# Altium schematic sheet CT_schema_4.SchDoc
size 422 x 246 mm
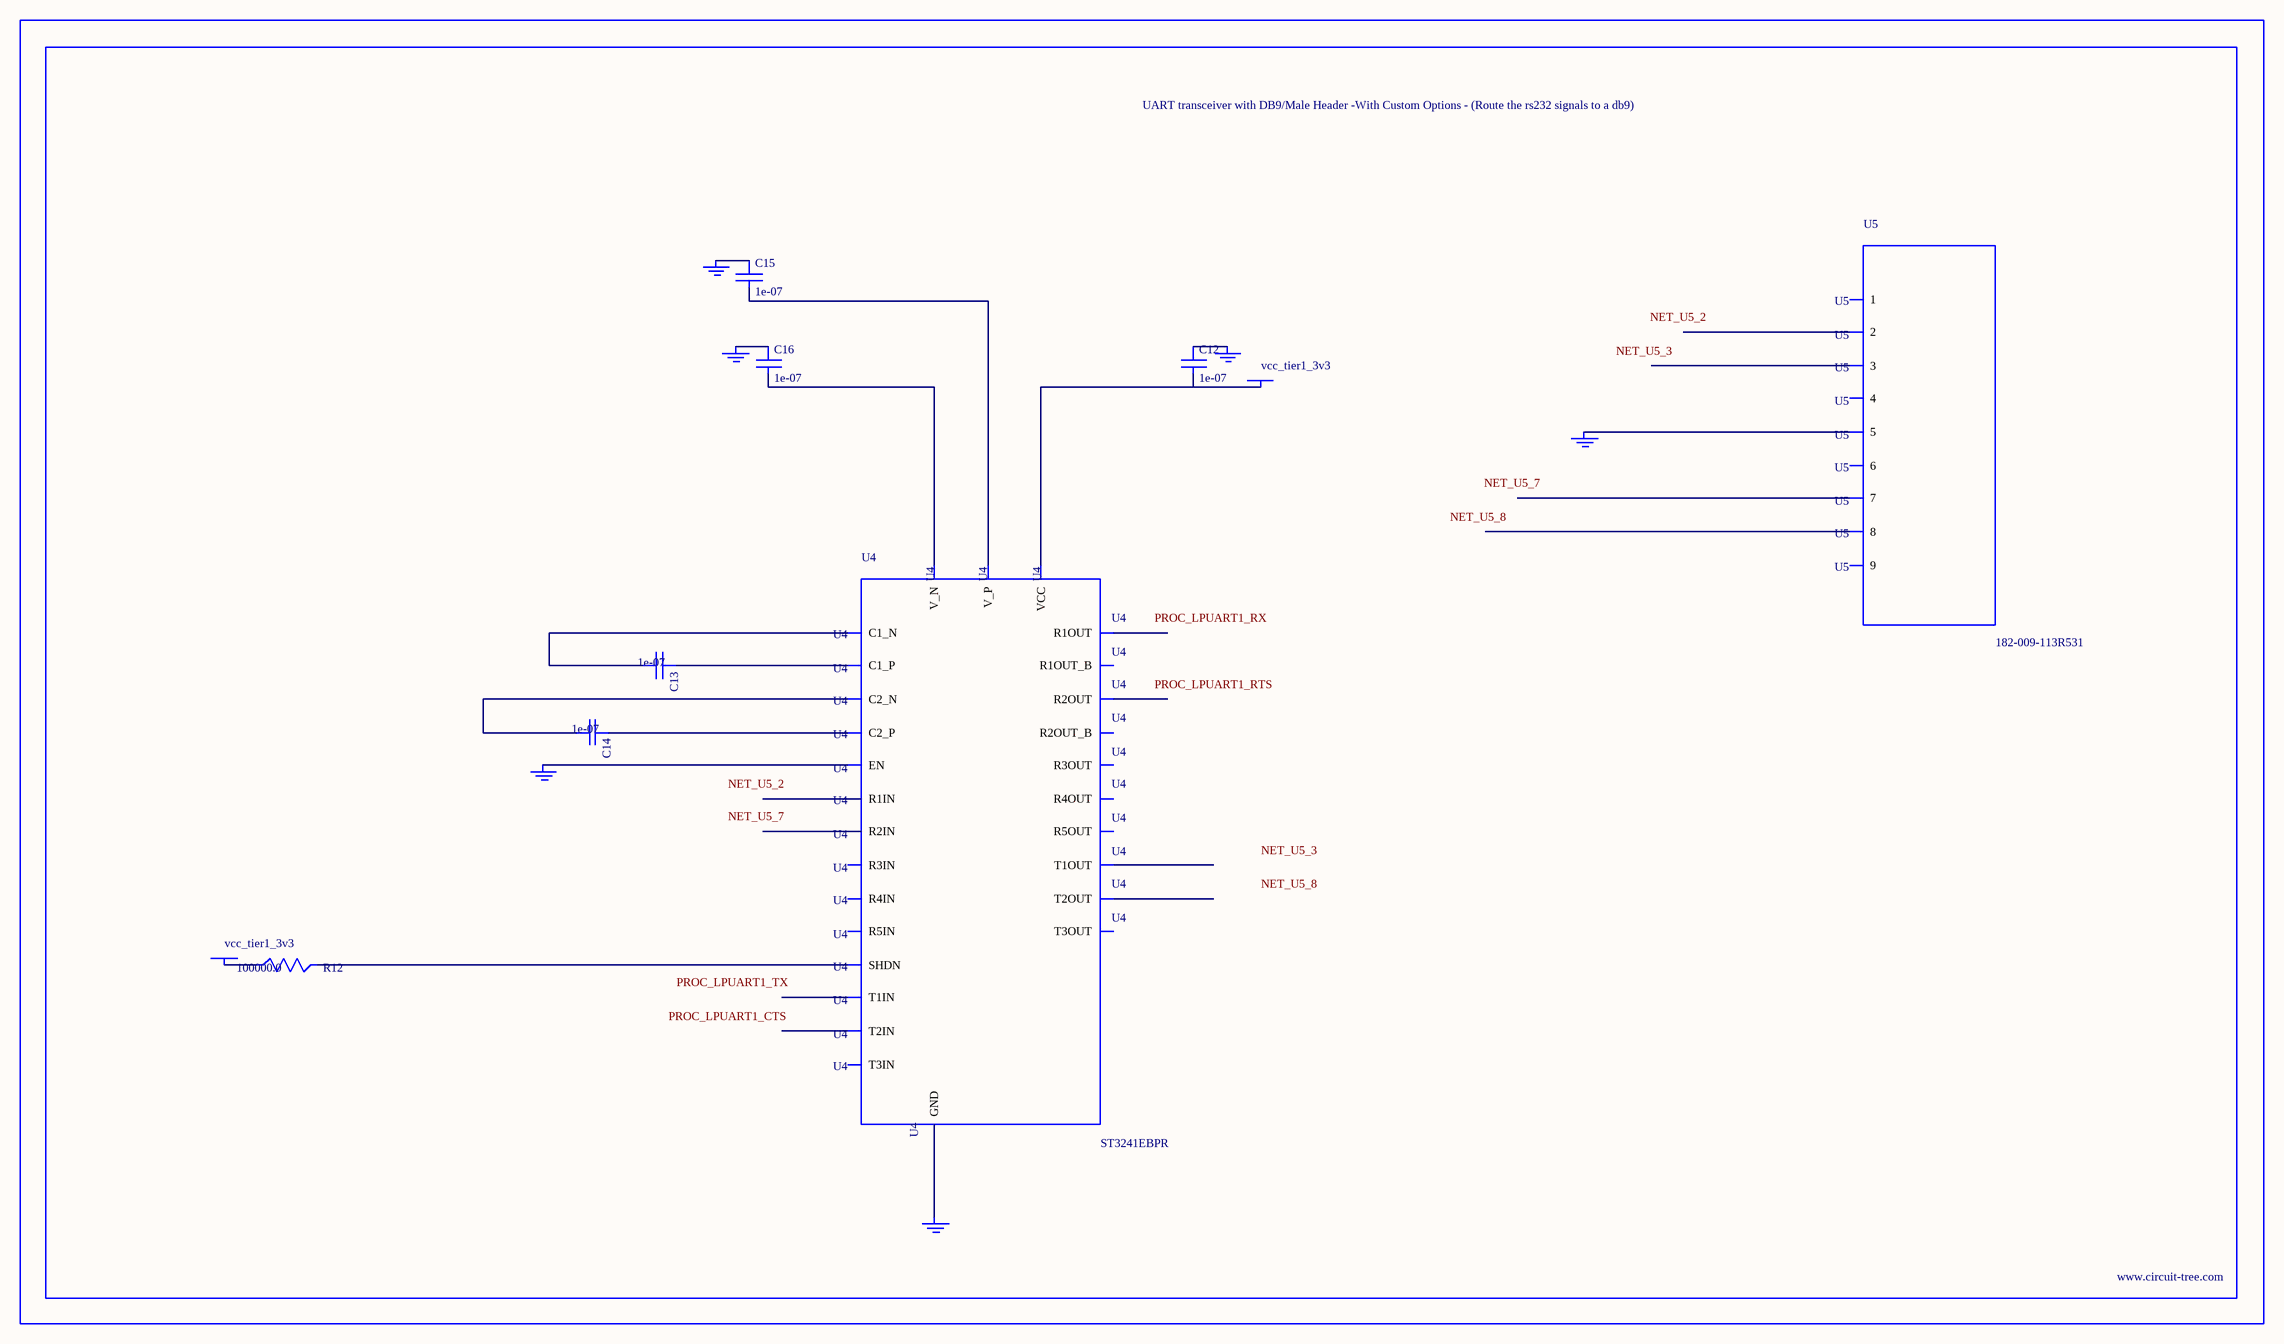
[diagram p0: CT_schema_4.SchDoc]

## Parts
BORDER3  (no value)
C12  1e-07  [C0402]
C13  1e-07  [C0402]
C14  1e-07  [C0402]
C15  1e-07  [C0402]
C16  1e-07  [C0402]
GND_INSTANCE_3_0  (no value)
GND_INSTANCE_3_1  (no value)
GND_INSTANCE_3_2  (no value)
GND_INSTANCE_3_3  (no value)
GND_INSTANCE_3_4  (no value)
GND_INSTANCE_3_5  (no value)
POWER_INSTANCE_3_0  vcc_tier1_3v3
POWER_INSTANCE_3_1  vcc_tier1_3v3
R12  100000.0  [R0603]
U4  ST3241EBPR  [SSOP-28]
U5  182-009-113R531  [182-009-MALE]

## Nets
NetC12_1: C12.1 GND_INSTANCE_3_2.0(GND)
NetC12_2: C12.2 POWER_INSTANCE_3_1.0(PWR) U4.26(VCC)
NetC13_1: C13.1 U4.28(C1_P)
NetC13_2: C13.2 U4.24(C1_N)
NetC14_1: C14.1 U4.1(C2_P)
NetC14_2: C14.2 U4.2(C2_N)
NetC15_1: C15.1 GND_INSTANCE_3_3.0(GND)
NetC15_2: C15.2 U4.27(V_P)
NetC16_1: C16.1 GND_INSTANCE_3_0.0(GND)
NetC16_2: C16.2 U4.3(V_N)
NetGND_INSTANCE_3_1_0: GND_INSTANCE_3_1.0(GND) U4.23(EN)
NetGND_INSTANCE_3_4_0: GND_INSTANCE_3_4.0(GND) U4.25(GND)
NetGND_INSTANCE_3_5_0: GND_INSTANCE_3_5.0(GND) U5.5
NetPOWER_INSTANCE_3_0_0: POWER_INSTANCE_3_0.0(PWR) R12.1
NetR12_2: R12.2 U4.22(SHDN)

Not connected (* = marked no-connect by the designer): U4 4(R1IN) 5(R2IN) 6(R3IN) 7(R4IN) 8(R5IN) 9(T1OUT) 10(T2OUT) 11(T3OUT) 12(T3IN) 13(T2IN) 14(T1IN) 15(R5OUT) 16(R4OUT) 17(R3OUT) 18(R2OUT) 19(R1OUT) 20(R2OUT_B) 21(R1OUT_B); U5 1 2 3 4 6 7 8 9

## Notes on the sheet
- Labels drawn without touching a wire or pin: NET_U5_2, NET_U5_3, NET_U5_7, NET_U5_8, PROC_LPUART1_CTS, PROC_LPUART1_RTS, PROC_LPUART1_RX, PROC_LPUART1_TX

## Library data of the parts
BORDER3 = BORDER_PAGE3
C12-C16 = C0402C104K3RACTU
GND_INSTANCE_3_0-GND_INSTANCE_3_5 = GND
POWER_INSTANCE_3_0 POWER_INSTANCE_3_1 = PWR
R12 = RC0603JR-07100KL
